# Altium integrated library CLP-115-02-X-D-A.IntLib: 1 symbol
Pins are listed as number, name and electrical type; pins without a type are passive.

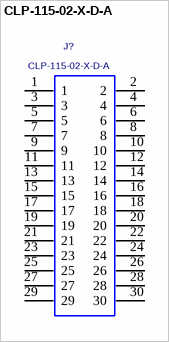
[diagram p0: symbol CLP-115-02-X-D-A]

## CLP-115-02-X-D-A
designator J?
LOW PROFILE SOCKET STRIP, .050"(1.27mm) PITCH, 30 PINS, ALIGNMENT PINS; MANUFACTURER: SAMTEC
footprint CLP-115-02-X-D-A
pins: 1, 2, 3, 4, 5, 6, 7, 8, 9, 10, 11, 12, 13, 14, 15, 16, 17, 18, 19, 20, 21, 22, 23, 24, 25, 26, 27, 28, 29, 30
